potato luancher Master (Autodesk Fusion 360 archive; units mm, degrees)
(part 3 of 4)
sketch "Sketch5" plane through (-5, 0, 0) normal (-1, 0, 0) x axis (0, -1, 0)
  line L1 (-319.7775, 137.65) -> (-315.5775, 141.85)
  line L2 (-319.7775, 135.65) -> (-319.7775, 137.65)
  line L3 (-313.4688, 135.65) -> (-319.7775, 135.65)
  line L4 (-313.4688, 131.35) -> (-313.4688, 135.65)
  line L5 (-278.9967, 136.85) -> (-278.9967, 123.4258)
  line L6 (-272.0357, 136.85) -> (-278.9967, 136.85)
  line L7 (-263.8509, 141.85) -> (-260.0435, 127.6406)
  line L8 (-296.5763, 141.85) -> (-279.0207, 162.9256)
  line L9 (-315.5775, 141.85) -> (-296.5763, 141.85)
  line L10 (-268.93, 125.2594) -> (-272.0357, 136.85)
  line L11 (-270.1342, 165.3063) -> (-263.8509, 141.85)
  arc A1 centre (-229.7424, 131.35) radius 83.7264 clockwise from (-311.5111, 113.35) to (-313.4688, 131.35)
  arc A2 centre (-274.4187, 51.1532) radius 72.4175 clockwise from (-311.5111, 113.35) to (-278.9967, 123.4258)
  arc A3 centre (-264.4867, 126.45) radius 4.6 clockwise from (-260.0435, 127.6406) to (-268.93, 125.2594)
  circle C1 centre (-264.4867, 126.45) radius 4.6
  arc A4 centre (-264.4867, 126.45) radius 39.2645 clockwise from (-279.0207, 162.9256) to (-270.1342, 165.3063)
  concentric A3 C1
extrude "Extrude3" add sketch "Sketch5" profile of A3 C1 blind 8 from offset 0.5
mirror "Mirror1" mirrorStitchTolerance 0.1
sketch "trigger pivot cleanup" plane through (0, 250.2367, 0) normal (0, -1, 0) x axis (1, 0, 0)
  line L1 (0, 173.45) -> (0, 116.35)
  line L2 (0, 116.35) -> (0, 173.45)
  line L3 (7.8919, 122.4898) -> (12.2469, 130.6973)
  line L4 (17.2316, 117.5341) -> (7.8919, 122.4898)
  line L5 (21.5865, 125.7415) -> (17.2316, 117.5341)
  line L6 (12.2469, 130.6973) -> (21.5865, 125.7415)
  line L7 (-9.193, 120.0119) -> (-12.5429, 130.6973)
  line L8 (-22.3256, 115.8947) -> (-9.193, 120.0119)
  line L9 (-25.6756, 126.58) -> (-22.3256, 115.8947)
  line L10 (-12.5429, 130.6973) -> (-25.6756, 126.58)
  arc A1 centre (0, 108.45) radius 65 clockwise from (-16, 171.45) to (0, 173.45)
  arc A2 centre (73.7256, 152.4) radius 91.7256 clockwise from (-11.4459, 118.35) to (-16, 171.45)
  arc A3 centre (0, 150.1021) radius 33.7521 clockwise from (0, 116.35) to (-11.4459, 118.35)
  arc A4 centre (0, 150.1021) radius 33.7521 clockwise from (11.4459, 118.35) to (0, 116.35)
  arc A5 centre (-73.7256, 152.4) radius 91.7256 clockwise from (16, 171.45) to (11.4459, 118.35)
  arc A6 centre (0, 108.45) radius 65 clockwise from (0, 173.45) to (16, 171.45)
  perpendicular L3 L4
  parallel L3 L5
  parallel L4 L6
  perpendicular L7 L8
  parallel L7 L9
  parallel L8 L10
extrude "Extrude8" cut sketch "trigger pivot cleanup" profile of A2 A5 L4 L5 L6 L8 L9 L10 against normal blind 20.32
combine "Combine1"
sketch "Sketch4" plane through (0, 0, 0) normal (1, 0, 0) x axis (0, 1, 0)
  line L1 (315.4811, 135.35) -> (315.4811, 131.35)
  line L2 (321.7775, 135.35) -> (315.4811, 135.35)
  line L3 (415.956, 135.35) -> (321.7775, 135.35)
  line L4 (415.956, 131.35) -> (415.956, 135.35)
  line L5 (315.4811, 131.35) -> (415.956, 131.35)
  line L6 (276.256, 131.35) -> (277.081, 131.35)
  line L7 (276.256, 131.35) -> (272.2367, 116.35)
  line L8 (250.2367, 116.35) -> (272.2367, 116.35)
  line L9 (250.2367, 173.45) -> (250.2367, 116.35)
  line L10 (415.956, 173.45) -> (250.2367, 173.45)
  line L11 (415.956, 169.45) -> (415.956, 173.45)
  line L12 (322.8085, 169.45) -> (415.956, 169.45)
  line L13 (254.2367, 169.45) -> (322.8085, 169.45)
  line L14 (254.2367, 120.35) -> (254.2367, 169.45)
  line L15 (269.1674, 120.35) -> (254.2367, 120.35)
  line L16 (269.1674, 120.35) -> (273.1866, 135.35)
  line L17 (275.635, 135.35) -> (273.1866, 135.35)
  line L18 (476.756, 88.9) -> (476.756, -88.9)
  line L19 (44.956, 88.9) -> (44.956, -88.9)
  line L20 (282.1228, 88.9) -> (476.756, 88.9)
  line L21 (466.756, 88.9) -> (415.956, 88.9)
  line L22 (415.956, 173.45) -> (456.3745, 173.45)
  line L23 (415.956, 88.9) -> (415.956, 173.45)
  line L24 (466.756, 88.9) -> (456.3745, 173.45)
  line L25 (322.7775, 173.45) -> (415.956, 173.45)
  line L26 (322.7775, 131.35) -> (322.7775, 173.45)
  line L27 (415.956, 131.35) -> (322.7775, 131.35)
  line L28 (415.956, 173.45) -> (415.956, 131.35)
  line L29 (410.7438, 131.35) -> (415.956, 88.9)
  line L30 (277.081, 131.35) -> (275.635, 135.35)
  point P21 (476.756, 88.9)
  point P24 (476.756, 88.9)
  point P26 (415.956, 88.9)
  point P6 (415.956, 131.35)
  point P32 (322.7775, 131.35)
  point P13 (415.956, 173.45)
  point P30 (415.956, 173.45)
  point P34 (410.7438, 131.35)
  point P27 (466.756, 88.9)
  point P4 (321.7775, 135.35)
  coincident P21 P24
  perpendicular L18 L20
  horizontal L21
  horizontal L22
  vertical L23
  coincident L20 P26
  coincident P6 L23
  horizontal L25
  vertical L26
  horizontal L27
  vertical L28
  coincident L5 P32
  coincident P13 P30
  coincident L22 P30
  coincident L27 P34
  parallel L24 L29
  dimension "d439" distance P26 P27 = 50.8
  dimension "d440" angle L22 L24 = 97 (= "90 deg + 7 deg")
  dimension "d441" distance P4 L26 = 1
work_plane "WorkPlane1" RotateAngle 90
split "Split2" bodies "left (1)", "right (1)"
remove_body "RemoveBody1"
remove_body "RemoveBody2"
sketch "Sketch5" plane through (0, 420.5316, 51.6348) normal (0, 0.9925, 0.1219) x axis (0, -0.1219, 0.9925)
  line L1 (-15.8537, 0) -> (0, 0)
  line L2 (26.4239, -25.4) -> (110.1588, -17.5985)
  line L3 (26.4239, 0) -> (26.4239, -25.4)
  line L4 (31.3541, 0) -> (116.5391, 0)
  line L5 (26.4239, 25.4) -> (110.1588, 17.5985)
  line L6 (26.4239, 0) -> (26.4239, 25.4)
  closed curve K1 centre (57.2419, 0)
  closed curve K2 centre (57.2419, 0)
  closed curve K3 centre (101.5219, -73.7256)
  closed curve K4 centre (101.5219, 73.7256)
  point P1 (0, 0)
  point P13 (0, 0)
  point P12 (31.2476, 0)
  point P15 (110.1588, -17.5985)
  point P17 (26.4239, 0)
  point P21 (110.1588, 17.5985)
  point P16 (26.4239, -25.4)
  point P20 (26.4239, 25.4)
  point P22 (26.4239, 0)
  point P3 (122.73, 0)
  coincident P1 P13
  horizontal L1
  coincident P12 L1
  coincident K4 P15
  vertical L3
  coincident L1 P17
  tangent K4 L2
  symmetric P15 L4 P21
  symmetric P16 L4 P20
  symmetric P17 L4 P22
  dimension "d447" distance P16 P17 = 25.4
  dimension "d451" distance P3 L6 = 96.3061
work_plane "WorkPlane19" AlongDistance -228.6
sketch "Sketch33" plane through (0, 478.8367, 0) normal (0, -1, 0) x axis (-1, 0, 0)
  line L1 (0, -77.8617) -> (25.4, -77.8617)
  line L2 (25.4, -77.8617) -> (17.5985, -160.9724)
  line L3 (-25.4, -77.8617) -> (-17.5985, -160.9724)
  line L4 (0, -77.8617) -> (-25.4, -77.8617)
  arc A1 centre (-73.7256, -152.4) radius 91.7256 clockwise from (16, -133.35) to (16, -171.45)
  arc A2 centre (0, -108.45) radius 65 clockwise from (16, -171.45) to (0, -173.45)
  arc A3 centre (0, -108.45) radius 65 clockwise from (0, -173.45) to (-16, -171.45)
  arc A4 centre (73.7256, -152.4) radius 91.7256 clockwise from (-16, -171.45) to (-16, -133.35)
loft "Loft4" sketch "Sketch5" + "Sketch33"
sketch "Sketch6" plane through (0, 0, 0) normal (1, 0, 0) x axis (0, 1, 0)
  line L1 (476.756, 88.9) -> (476.756, -88.9)
  line L2 (44.956, 88.9) -> (44.956, -88.9)
  line L3 (364.3526, 88.9) -> (476.756, 88.9)
  line L4 (405.8201, 171.45) -> (417.3113, 77.8617)
  line L5 (478.8367, 171.45) -> (405.8201, 171.45)
  line L6 (478.8367, 171.45) -> (478.8367, 77.8617)
  line L7 (417.3113, 77.8617) -> (478.8367, 77.8617)
  line L8 (405.5745, 173.45) -> (405.8201, 171.45)
  line L9
  line L10 (478.8367, 173.45) -> (478.8367, 171.45)
  line L11 (405.8201, 171.45) -> (478.8367, 171.45)
  line L12 (405.5745, 173.45) -> (478.8367, 173.45)
  line L13 (466.756, 88.9) -> (415.956, 88.9)
  line L14 (472.7065, 40.4371) -> (454.8153, 186.1492)
  line L15 (487.1508, 88.9) -> (407.438, 88.9)
  line L16 (487.1508, 75.9737) -> (487.1508, 88.9)
  line L17 (407.438, 75.9737) -> (487.1508, 75.9737)
  line L18 (407.438, 88.9) -> (407.438, 75.9737)
  point P3 (476.756, 88.9)
  point P6 (476.756, 88.9)
  point P15 (478.8367, 173.45)
  point P16 (478.8367, 173.45)
  point P13 (405.5745, 173.45)
  point P17 (405.5745, 173.45)
  point P21 (415.956, 88.9)
  point P22 (415.956, 88.9)
  point P23 (466.756, 88.9)
  point P26 (407.438, 88.9)
  coincident P3 P6
  perpendicular L1 L3
  coincident P15 P16
  coincident P13 P17
  coincident L4 P21
  coincident L3 P21
  coincident P21 P22
  parallel L3 L13
  coincident P23 L14
  parallel L4 L14
  horizontal L15
  vertical L16
  horizontal L17
  vertical L18
  coincident L3 P26
  dimension "d452" distance P22 P23 = 50.8
extrude "Extrude5" cut sketch "Sketch6" profile of L1 L3 L5 L6 L7 L9 L10 L11 L12 L14 L15 distance 88.9
revolve "Revolve1" sketch "Sketch6" AlongAngle 360
shell "Shell2" innerThickness 4
split "Split3"
work_plane "WorkPlane2" AlongDistance -101.6
sketch "Sketch7" plane through (0, 351.8367, 0) normal (0, -1, 0) x axis (-1, 0, 0)
  arc A1 centre (0, -196.35) radius 61 clockwise from (-12.5765, -136.6605) to (0, -135.35)
  arc A2 centre (73.7256, -152.4) radius 87.7256 clockwise from (-12.5765, -168.1395) to (-12.5765, -136.6605)
  arc A3 centre (0, -108.45) radius 61 clockwise from (0, -169.45) to (-12.5765, -168.1395)
  arc A4 centre (0, -108.45) radius 61 clockwise from (12.5765, -168.1395) to (0, -169.45)
  arc A5 centre (-73.7256, -152.4) radius 87.7256 clockwise from (12.5765, -136.6605) to (12.5765, -168.1395)
  arc A6 centre (0, -196.35) radius 61 clockwise from (0, -135.35) to (12.5765, -136.6605)
  arc A7 centre (0, -196.35) radius 65 clockwise from (-6, -131.6275) to (0, -131.35)
  arc A8 centre (0, -196.35) radius 65 clockwise from (0, -131.35) to (6, -131.6275)
extrude "Extrude6" cut sketch "Sketch7" profile of A1 A2 A3 A4 A5 A6 against normal blind 76.2
combine "Combine2"
combine "Combine3"
face "Face1" sketch "Sketch4"
sketch "Sketch6" plane through (0, 0, 0) normal (1, 0, 0) x axis (0, 1, 0)
  line L1 (322.7775, 131.35) -> (410.7438, 131.35)
  line L2 (322.7775, 173.45) -> (322.7775, 131.35)
  line L3 (456.3745, 173.45) -> (322.7775, 173.45)
  line L4 (466.756, 88.9) -> (456.3745, 173.45)
  line L5 (415.956, 88.9) -> (466.756, 88.9)
  line L6 (410.7438, 131.35) -> (415.956, 88.9)
  line L7 (322.4775, 173.45) -> (322.7775, 173.45)
  line L8 (322.4775, 131.35) -> (322.4775, 173.45)
  line L9 (322.7775, 131.35) -> (322.4775, 131.35)
  line L10 (322.7775, 173.45) -> (322.7775, 131.35)
  point P4 (322.7775, 173.45)
  point P8 (322.7775, 173.45)
  point P3 (322.7775, 131.35)
  point P11 (322.7775, 131.35)
  point P10 (322.4775, 131.35)
  horizontal L7
  vertical L8
  horizontal L9
  vertical L10
  coincident P4 P8
  coincident P3 P11
  dimension "d442" distance P10 P11 = 0.3
extrude "Extrude4" cut sketch "Sketch6" distance 3.175
work_plane "WorkPlane21" AlongDistance 130.592 (= "120.592 mm + 10 mm")
sketch "Sketch1" plane through (0, 130.592, 0) normal (0, 1, 0) x axis (1, 0, 0)
  line L1 (-66.675, -62.217) -> (-63.5, -62.217)
  line L2 (-114.8533, -109.7881) -> (0, 0)
  line L3 (-71.5066, -77.9814) -> (-79.2206, -75.7268)
  line L4 (-65.6971, -72.4281) -> (-71.5066, -77.9814)
  line L5 (-67.6016, -64.6203) -> (-65.6971, -72.4281)
  line L6 (-75.3157, -62.3658) -> (-67.6016, -64.6203)
  line L7 (-81.1251, -67.9191) -> (-75.3157, -62.3658)
  line L8 (-79.2206, -75.7268) -> (-81.1251, -67.9191)
  line L9 (-64.2629, -61.4288) -> (-61.2638, -73.7238)
  line L10 (-76.4102, -57.8786) -> (-64.2629, -61.4288)
  line L11 (-85.5585, -66.6234) -> (-76.4102, -57.8786)
  line L12 (-82.5594, -78.9184) -> (-85.5585, -66.6234)
  line L13 (-70.412, -82.4686) -> (-82.5594, -78.9184)
  line L14 (-61.2638, -73.7238) -> (-70.412, -82.4686)
  circle C1 centre (0, 0) radius 88.9
  point P1 (0, 0)
  point P4 (0, 0)
  point P6 (-65.0875, -62.217)
  point P14 (-73.4111, -70.1736)
  point P8 (-79.2206, -75.7268)
  point P16 (-64.2629, -61.4288)
  coincident P1 P4
  midpoint L1 P6
  coincident L2 P6
  coincident L2 P14
  coincident L2 P8
  coincident C1 P16
  dimension "d486" distance P14 L8 = 6.96 (= "13.92 mm / 2")
  dimension "d487" = 4
work_plane "WorkPlane1" RotateAngle 90
sketch "Sketch2" plane through (-7.5732, 0, -7.9226) normal (-0.691, 0, -0.7229) x axis (-0.7229, 0, 0.691)
  line L1 (-88.9, 476.756) -> (88.9, 476.756)
  line L2 (-88.9, 44.956) -> (88.9, 44.956)
  line L3 (88.9, 476.756) -> (88.9, 44.956)
  line L4 (107.8833, 130.592) -> (95.2278, 130.592)
  line L5 (114.211, 130.592) -> (107.8833, 130.592)
  line L6 (95.2278, 130.592) -> (88.9, 130.592)
  line L7 (122.0173, 164.7525) -> (102.9, 130.592)
  line L8 (88.9, 170.592) -> (122.0173, 164.7525)
  line L9 (102.4196, 168.2081) -> (118.078, 165.4471)
  line L10 (111.2166, 218.0985) -> (102.4196, 168.2081)
  line L11 (126.875, 215.3375) -> (111.2166, 218.0985)
  line L12 (118.078, 165.4471) -> (126.875, 215.3375)
  line L13 (107.1949, 195.2903) -> (108.0631, 200.2144)
  line L14 (93.9, 197.6346) -> (107.1949, 195.2903)
  line L15 (94.7682, 202.5586) -> (93.9, 197.6346)
  line L16 (108.0631, 200.2144) -> (94.7682, 202.5586)
  line L17 (88.9, 130.592) -> (102.9, 130.592)
  line L18 (124.4623, 215.7629) -> (113.6294, 217.6731)
  line L19 (133.1447, 265.0033) -> (124.4623, 215.7629)
  line L20 (122.3118, 266.9134) -> (133.1447, 265.0033)
  line L21 (113.6294, 217.6731) -> (122.3118, 266.9134)
  line L22 (103.4044, 168.0345) -> (117.0932, 165.6208)
  line L23 (88.9, 130.592) -> (88.9, 170.592)
  line L24 (86.9, 130.592) -> (88.9, 130.592)
  line L25 (86.9, 170.592) -> (86.9, 130.592)
  line L26 (88.9, 170.592) -> (86.9, 170.592)
  point P4 (88.9, 44.956)
  point P6 (88.9, 44.956)
  point P2 (88.9, 476.756)
  point P7 (88.9, 476.756)
  point P14 (88.9, 170.592)
  point P20 (107.1949, 195.2903)
  point P23 (94.3341, 200.0966)
  point P24 (88.9, 130.592)
  point P8 (95.2278, 130.592)
  point P29 (119.0458, 216.718)
  point P30 (119.0458, 216.718)
  point P31 (117.0932, 165.6208)
  point P32 (103.4044, 168.0345)
  point P13 (122.0173, 164.7525)
  point P11 (88.9, 130.592)
  point P33 (88.9, 130.592)
  point P15 (118.078, 165.4471)
  point P18 (126.875, 215.3375)
  point P16 (102.4196, 168.2081)
  point P21 (93.9, 197.6346)
  point P22 (94.7682, 202.5586)
  point P10 (114.211, 130.592)
  point P27 (133.1447, 265.0033)
  point P28 (122.3118, 266.9134)
  point P26 (124.4623, 215.7629)
  point P12 (102.9, 130.592)
  point P35 (86.9, 170.592)
  coincident P4 P6
  coincident P2 P7
  coincident L3 P14
  perpendicular L9 L10
  parallel L9 L11
  parallel L10 L12
  perpendicular L13 L14
  parallel L13 L15
  parallel L14 L16
  coincident L10 P20
  parallel L10 L13
  midpoint L15 P23
  parallel L8 L9
  coincident L3 P24
  perpendicular L3 L17
  coincident P8 L17
  perpendicular L18 L19
  parallel L18 L20
  parallel L19 L21
  parallel L12 L19
  midpoint L18 P29
  midpoint L11 P30
  coincident P29 P30
  coincident L9 P31
  coincident L9 P32
  midpoint L9 L22
  coincident P13 L9
  perpendicular L23 L24
  parallel L23 L25
  parallel L24 L26
  coincident P11 P33
  dimension "d490" distance P15 P18 = 50.66
  dimension "d491" distance P15 P16 = 15.9
  dimension "d492" distance L10 L15 = 13.5
  dimension "d493" distance L9 P23 = 30
  dimension "d495" distance P21 P22 = 5
  dimension "d497" angle L3 L10 = 10
  dimension "d498" distance P10 P11 = 25.311
  dimension "d500" distance L3 P21 = 5
  dimension "d501" distance P14 L17 = 40
  dimension "d502" distance P27 P28 = 11
  dimension "d504" distance P26 P27 = 50
  dimension "d505" distance P31 P32 = 13.9
  dimension "d506" distance P13 P31 = 5
  dimension "d507" distance L3 P12 = 14
  dimension "d511" distance P14 P35 = 2
face "Face1" sketch "Sketch2" bodies "right"
work_plane "WorkPlane1" RotateAngle 90
mirror "Mirror1" mirrorStitchTolerance 0.1 bodies "left"
sketch "Sketch1" plane through (-16.4132, -12.7068, 15.6894) normal (-0.6308, -0.4884, 0.603) x axis (0.6122, -0.7907, 0)
  line L1 (-144.1616, 79.3929) -> (-179.6329, 95.9517)
  line L2 (-142.8185, 82.2699) -> (-144.1616, 79.3929)
  line L3 (-178.2899, 98.8286) -> (-142.8185, 82.2699)
  line L4 (-179.6329, 95.9517) -> (-178.2899, 98.8286)
  line L5 (-188.9051, 76.0893) -> (-153.4337, 59.5305)
  line L6 (-190.2481, 73.2123) -> (-188.9051, 76.0893)
  line L7 (-154.7767, 56.6536) -> (-190.2481, 73.2123)
  line L8 (-153.4337, 59.5305) -> (-154.7767, 56.6536)
  line L9 (-190.2481, 73.2123) -> (-178.2899, 98.8286)
  line L10 (-154.7767, 56.6536) -> (-190.2481, 73.2123)
  line L11 (-142.8185, 82.2699) -> (-154.7767, 56.6536)
  line L12 (-178.2899, 98.8286) -> (-142.8185, 82.2699)
  point P8 (-190.2481, 73.2123)
  point P11 (-190.2481, 73.2123)
  point P5 (-178.2899, 98.8286)
  point P10 (-178.2899, 98.8286)
  perpendicular L9 L10
  parallel L9 L11
  parallel L10 L12
  coincident P8 P11
  perpendicular L7 L9
  coincident P5 P10
face "Face2" sketch "Sketch1" bodies "top"
sketch "Sketch2" plane through (0, 130.592, 0) normal (0, -1, 0) x axis (1, 0, 0)
  line L1 (-55.2439, 67.9694) -> (-66.8098, 79.0252)
  line L2 (-64.6159, 81.3203) -> (-53.05, 70.2645)
  line L3 (-66.8098, 79.0252) -> (-64.6159, 81.3203)
  line L4 (-81.9562, 63.18) -> (-70.3904, 52.1242)
  line L5 (-84.1501, 60.8849) -> (-81.9562, 63.18)
  line L6 (-72.5842, 49.8291) -> (-84.1501, 60.8849)
  line L7 (-84.1501, 60.8849) -> (-64.6159, 81.3203)
  line L8 (-72.5842, 49.8291) -> (-84.1501, 60.8849)
  line L9 (-53.05, 70.2645) -> (-72.5842, 49.8291)
  line L10 (-64.6159, 81.3203) -> (-53.05, 70.2645)
  line L11 (-53.05, 70.2645) -> (-55.2439, 67.9694)
  line L12 (-70.3904, 52.1242) -> (-72.5842, 49.8291)
  point P8 (-84.1501, 60.8849)
  point P11 (-84.1501, 60.8849)
  point P5 (-64.6159, 81.3203)
  point P10 (-64.6159, 81.3203)
  point P9 (-72.5842, 49.8291)
  perpendicular L7 L8
  parallel L7 L9
  parallel L8 L10
  coincident P8 P11
  perpendicular L6 L7
  coincident P5 P10
  coincident P9 L9
face "Face3" sketch "Sketch2" bodies "back"
sketch "Sketch3" plane through (-23.0259, 180.6508, 22.0104) normal (-0.1255, 0.9848, 0.12) x axis (-0.992, -0.1264, 0)
  line L1 (59.1509, 70.7356) -> (34.6654, 47.6855)
  line L2 (56.9747, 73.0474) -> (59.1509, 70.7356)
  line L3 (32.4891, 49.9973) -> (56.9747, 73.0474)
  line L4 (76.3521, 52.4632) -> (56.9747, 73.0474)
  line L5 (78.5349, 54.5181) -> (76.3521, 52.4632)
  line L6 (59.1574, 75.1022) -> (78.5349, 54.5181)
  line L7 (56.9747, 73.0474) -> (59.1574, 75.1022)
  line L8 (49.6903, 31.7249) -> (74.1758, 54.775)
  line L9 (76.3521, 52.4632) -> (51.8665, 29.4131)
  line L10 (74.1758, 54.775) -> (76.3521, 52.4632)
  line L11 (78.5349, 54.5181) -> (51.8665, 29.4131)
  line L12 (59.1574, 75.1022) -> (78.5349, 54.5181)
  line L13 (32.4891, 49.9973) -> (59.1574, 75.1022)
  line L14 (51.8665, 29.4131) -> (32.4891, 49.9973)
  line L15 (34.6654, 47.6855) -> (32.4891, 49.9973)
  line L16 (51.8665, 29.4131) -> (49.6903, 31.7249)
  line L17 (48.2561, 30.3749) -> (49.6903, 31.7249)
  line L18 (50.4324, 28.0631) -> (48.2561, 30.3749)
  line L19 (51.8665, 29.4131) -> (50.4324, 28.0631)
  line L20 (49.6903, 31.7249) -> (51.8665, 29.4131)
  line L21 (34.6654, 47.6855) -> (33.2312, 46.3354)
  line L22 (32.4891, 49.9973) -> (34.6654, 47.6855)
  line L23 (31.055, 48.6472) -> (32.4891, 49.9973)
  line L24 (33.2312, 46.3354) -> (31.055, 48.6472)
  line L25 (48.2561, 30.3749) -> (33.2312, 46.3354)
  point P8 (78.5349, 54.5181)
  point P15 (78.5349, 54.5181)
  point P12 (51.8665, 29.4131)
  point P14 (51.8665, 29.4131)
  point P22 (33.2312, 46.3354)
  point P26 (33.2312, 46.3354)
  point P19 (48.2561, 30.3749)
  point P27 (48.2561, 30.3749)
  perpendicular L11 L12
  parallel L11 L13
  parallel L12 L14
  coincident P8 P15
  perpendicular L6 L11
  coincident P12 P14
  coincident P22 P26
  coincident P19 P27
face "Face4" sketch "Sketch3" bodies "face"
sketch "Sketch4" plane through (-23.4245, 183.7776, 22.3914) normal (-0.1255, 0.9848, 0.12) x axis (-0.992, -0.1264, 0)
  line L1 (78.5349, 54.5181) -> (50.4324, 28.0631)
  line L2 (59.1574, 75.1022) -> (78.5349, 54.5181)
  line L3 (31.055, 48.6472) -> (59.1574, 75.1022)
  line L4 (50.4324, 28.0631) -> (31.055, 48.6472)
  line L5 (40.7437, 38.3551) -> (68.8462, 64.8101)
  line L6 (51.8665, 29.4131) -> (76.3521, 52.4632)
  line L7 (56.9747, 73.0474) -> (76.3521, 52.4632)
  circle C1 centre (58.7013, 55.26) radius 6.935
  circle C2 centre (58.7013, 55.26) radius 4.15
  point P7 (68.8462, 64.8101)
  point P8 (40.7437, 38.3551)
  point P6 (58.7013, 55.26)
  point P9 (63.7509, 60.0136)
  point P11 (76.3521, 52.4632)
  point P13 (76.3521, 52.4632)
  point P14 (56.9747, 73.0474)
  midpoint L2 P7
  midpoint L4 P8
  coincident P6 L5
  coincident L5 P9
  coincident C1 P9
  concentric C1 C2
  coincident P11 P13
  coincident L3 P14
  perpendicular L3 L7
  dimension "d513" diameter C1 = 13.87
  dimension "d514" diameter C2 = 8.3
  dimension "d515" distance P9 L7 = 4
extrude "Extrude1" cut sketch "Sketch4" profile of C2 against normal blind 3.175
offset_faces "OffsetFaces1" distance -1
loft "Loft1"
sketch "Sketch46" plane through (-23.4245, 183.7776, 22.3914) normal (-0.1255, 0.9848, 0.12) x axis (-0.992, -0.1264, 0)
  line L1 (77.8068, 53.8326) -> (50.4324, 28.0631)
  line L2 (58.4293, 74.4168) -> (77.8068, 53.8326)
  line L3 (31.055, 48.6472) -> (58.4293, 74.4168)
  line L4 (50.4324, 28.0631) -> (31.055, 48.6472)
  circle C1 centre (58.7013, 55.26) radius 4.15
extrude "Extrude2" cut sketch "Sketch46" profile of C1 against normal blind 5.175 (magnitude of "-0.125 in - 2 mm")
sketch "inlet body jig base" plane through (-62.8171, 0, 60.0468) normal (0.7229, 0, -0.691) x axis (0, 1, 0)
  line L1 (130.592, 10.96) -> (170.592, 10.96)
  line L2 (130.592, -10.96) -> (130.592, 10.96)
  line L3 (170.592, -10.96) -> (130.592, -10.96)
  line L4 (170.592, 10.96) -> (170.592, -10.96)
  line L5 (170.36, -10.96) -> (130.592, 10.96)
  line L6 (144.3456, 4.7162) -> (145.7598, 6.1304)
  line L7 (155.1922, -6.1304) -> (144.3456, 4.7162)
  line L8 (156.6064, -4.7162) -> (155.1922, -6.1304)
  line L9 (145.7598, 6.1304) -> (156.6064, -4.7162)
  line L10 (155.1922, -6.1304) -> (145.7598, 6.1304)
  line L11 (150.476, 13.5357) -> (150.476, 0)
  line L12 (155.1922, 6.1304) -> (144.3456, -4.7162)
  line L13 (145.7598, -6.1304) -> (156.6064, 4.7162)
  line L14 (156.6064, 4.7162) -> (155.1922, 6.1304)
  line L15 (144.3456, -4.7162) -> (145.7598, -6.1304)
  point P3 (130.592, 10.96)
  point P6 (130.592, 10.96)
  point P7 (170.36, -10.96)
  point P8 (150.476, 0)
  point P13 (150.476, 0)
  point P14 (150.476, 0)
  point P9 (145.7598, 6.1304)
  point P17 (155.1922, 6.1304)
  point P10 (144.3456, 4.7162)
  point P18 (156.6064, 4.7162)
  point P11 (155.1922, -6.1304)
  point P19 (145.7598, -6.1304)
  point P12 (156.6064, -4.7162)
  point P16 (144.3456, -4.7162)
  coincident P3 P6
  coincident L3 P7
  midpoint L5 P8
  perpendicular L6 L7
  parallel L6 L8
  parallel L7 L9
  midpoint L10 P13
  coincident P8 P13
  coincident P13 P14
  vertical L11
  symmetric P9 L11 P17
  symmetric P10 L11 P18
  symmetric P11 L11 P19
  symmetric P12 L11 P16
  dimension "d572" distance P11 P12 = 2
  dimension "d573" distance P9 P12 = 15.3394
  dimension "d574" angle L1 L9 = 45
extrude "Extrude2" cut sketch "inlet body jig base" profile of L6 L7 L8 L9 L12 L13 L14 L15 against normal blind 1
hole "Hole1" HoleDepth 17.78 HoleDiameter 10.8204 TipAngle 180
remove_instance "RemoveInstance1"
sketch "Sketch3" plane through (0, 0, 0) normal (0, 0, 1) x axis (1, 0, 0)
  circle C1 centre (13.7901, 221.4962) radius 17.4625
  circle C2 centre (13.7901, 221.4962) radius 3.325
  concentric C1 C2
  dimension "d586" diameter C1 = 34.925
  dimension "d587" diameter C2 = 6.65 (= "0.25 in + 0.3 mm")
face "Face1" sketch "Sketch3"
joint "Assemble1" alignAngle 0 alignOffsetX 0 alignOffsetY 0 alignOffsetZ 0
sketch "claw init" plane through (-22.4118, 0, 40.4319) normal (0.4848, 0, -0.8746) x axis (0.8746, 0, 0.4848)
  line L1 (24.13, 0) -> (-24.13, 0)
  line L2 (88.9, -44.956) -> (-88.9, -44.956)
  line L3 (-40.4813, 68.326) -> (-34.4813, 68.326)
  line L4 (-32.0572, 81.026) -> (-24.246, 100.743)
  line L5 (-70.2879, 68.326) -> (-34.4813, 68.326)
  line L6 (-47.2124, 70.5709) -> (-34.4813, 68.326)
  line L7 (-42.4813, 47.6884) -> (-42.4813, 82.326)
  line L8 (0, -22.5) -> (0, -1.75)
  line L9 (88.9, 177.8645) -> (-88.9, 177.8645)
  line L10 (88.9, -41.2125) -> (88.9, 177.8645)
  line L11 (-88.9, -41.2125) -> (88.9, -41.2125)
  line L12 (-88.9, 177.8645) -> (-88.9, -41.2125)
  line L13 (-55.1813, 69.626) -> (-42.4813, 69.626)
  line L14 (-55.1813, 13.4637) -> (-55.1813, 69.626)
  line L15 (-42.4813, 13.4637) -> (-55.1813, 13.4637)
  line L16 (-42.4813, 69.626) -> (-42.4813, 13.4637)
  line L17 (-42.4813, 47.6884) -> (-30.4657, 23.9497)
  line L18 (-55.1813, 44.6574) -> (-41.7968, 18.2143)
  line L19 (-40.4813, 68.326) -> (-34.4813, 68.326)
  line L20 (-55.1813, 44.6574) -> (-42.4813, 47.6884)
  line L21 (-48.8313, 46.1729) -> (-34.4813, 68.326)
  line L22 (-36.1313, 21.082) -> (-48.8313, 46.1729)
  line L23 (-46.0984, 26.7127) -> (-34.7672, 32.4481)
  circle C1 centre (29.561, 75.0731) radius 1.61
  circle C2 centre (13.1559, 95.6445) radius 1.61
  circle C3 centre (23.7061, 49.421) radius 1.61
  circle C4 centre (-13.1559, 95.6445) radius 1.61
  circle C5 centre (-29.561, 75.0731) radius 1.61
  circle C6 centre (0, 38.0048) radius 1.61
  circle C7 centre (-23.7061, 49.421) radius 1.61
  arc A1 centre (0, 68.326) radius 34.4813 clockwise from (-34.4813, 68.326) to (-32.0572, 81.026)
  arc A2 centre (0, 68.326) radius 40.4813 clockwise from (-24.246, 100.743) to (-40.4813, 68.326)
  arc A3 centre (-50.7312, 68.326) radius 16.25 clockwise from (-42.4813, 82.326) to (-34.4813, 68.326)
  arc A4 centre (-42.4813, 69.626) radius 12.7 clockwise from (-55.1813, 69.626) to (-42.4813, 82.326)
  arc A5 centre (-24.13, -69.1365) radius 69.1365 clockwise from (-88.9, -44.956) to (-24.13, 0)
  circle C8 centre (-36.1313, 21.082) radius 3.175
  circle C9 centre (-36.1313, 21.082) radius 6.35
  circle C10 centre (-48.8313, 46.1729) radius 3.175
  arc A6 centre (29.561, 75.0731) radius 3 clockwise from (28.0113, 72.5044) to (27.0503, 76.7151)
  arc A7 centre (0, 68.326) radius 28.3213 clockwise from (28.0113, 72.5044) to (23.4244, 52.4078)
  arc A8 centre (23.7061, 49.421) radius 3 clockwise from (20.7316, 49.031) to (23.4244, 52.4078)
  arc A9 centre (0, 68.326) radius 28.3213 clockwise from (20.7316, 49.031) to (2.1595, 40.0872)
  arc A10 centre (0, 38.0048) radius 3 clockwise from (-2.1595, 40.0872) to (2.1595, 40.0872)
  arc A11 centre (0, 68.326) radius 28.3213 clockwise from (-2.1595, 40.0872) to (-20.7316, 49.031)
  arc A12 centre (-23.7061, 49.421) radius 3 clockwise from (-23.4244, 52.4078) to (-20.7316, 49.031)
  arc A13 centre (0, 68.326) radius 28.3213 clockwise from (-23.4244, 52.4078) to (-28.0113, 72.5044)
  arc A14 centre (-29.561, 75.0731) radius 3 clockwise from (-27.0503, 76.7151) to (-28.0113, 72.5044)
  arc A15 centre (0, 68.326) radius 28.3213 clockwise from (-27.0503, 76.7151) to (-14.198, 92.8313)
  arc A16 centre (-13.1559, 95.6445) radius 3 clockwise from (-10.3067, 94.7052) to (-14.198, 92.8313)
  arc A17 centre (0, 68.326) radius 28.3213 clockwise from (-10.3067, 94.7052) to (10.3067, 94.7052)
  arc A18 centre (13.1559, 95.6445) radius 3 clockwise from (14.198, 92.8313) to (10.3067, 94.7052)
  arc A19 centre (0, 68.326) radius 28.3213 clockwise from (14.198, 92.8313) to (27.0503, 76.7151)
  point P15 (-34.4813, 68.326)
  point P18 (-34.4813, 68.326)
  point P20 (-34.4813, 68.326)
  point P25 (0, 27.8447)
  point P10 (0, 68.326)
  point P32 (0, 68.326)
  point P33 (0, 177.8645)
  point P34 (-42.4813, 69.626)
  point P39 (-55.1813, 69.626)
  point P38 (-42.4813, 69.626)
  point P2 (-24.13, 0)
  point P41 (-24.13, 0)
  point P4 (-88.9, -44.956)
  point P40 (-88.9, -44.956)
  point P45 (-30.4657, 23.9497)
  point P46 (-41.7968, 18.2143)
  point P47 (-55.1813, 44.6574)
  point P50 (-48.8313, 46.1729)
  point P51 (-48.8313, 46.1729)
  point P48 (-34.4813, 68.326)
  point P52 (-34.4813, 68.326)
  point P53 (-48.8313, 46.1729)
  point P54 (-48.8313, 46.1729)
  point P43 (-36.1313, 21.082)
  point P55 (-36.1313, 21.082)
  point P56 (-34.7672, 32.4481)
  point P57 (-46.0984, 26.7127)
  point P58 (-33.2636, 15.4164)
  point P16 (-40.4813, 68.326)
  point P22 (-42.4813, 82.326)
  point P28 (-88.9, 177.8645)
  point P29 (88.9, 177.8645)
  point P35 (-55.1813, 69.626)
  point P49 (-40.4813, 68.326)
  coincident P15 P18
  parallel L3 L5
  coincident P15 P20
  vertical L7
  tangent A1 A3
  coincident A2 P25
  coincident P25 L8
  horizontal L9
  perpendicular L9 L10
  parallel L9 L11
  parallel L10 L12
  coincident P10 P32
  midpoint L9 P33
  coincident L8 P33
  horizontal L13
  vertical L14
  horizontal L15
  vertical L16
  coincident L7 P34
  coincident L13 P39
  coincident P34 P38
  coincident L14 P39
  coincident P2 P41
  coincident P4 P40
  coincident C9 P45
  tangent C9 L17
  coincident C9 P46
  tangent C9 L18
  coincident L14 P47
  parallel L17 L18
  tangent L16 C9
  midpoint L20 P50
  coincident P50 P51
  coincident P48 P52
  coincident P51 P53
  coincident P51 P54
  coincident P43 P55
  coincident L17 P56
  coincident L18 P57
  perpendicular L18 L23
  coincident C9 P58
  coincident L22 P58
  dimension "d475" angle L5 L6 = 10
  dimension "d476" distance P16 L7 = 2
  dimension "d477" distance L5 P22 = 14
  dimension "d478" distance P28 P29 = 177.8 (= "7")
  dimension "d519" distance P34 P35 = 12.7
  dimension "d520" diameter C8 = 6.35
  dimension "d521" distance C8 = 3.175
  dimension "d535" distance P48 P49 = 6
  dimension "d536" diameter C10 = 6.35
  dimension "d537" distance L23 P58 = 15.875
  dimension "d756" distance P54 P55 = 28.1219
  dimension "d757" distance L13 P51 = 23.4531 (= "1.0033510731 in - 0.08 in")
face "Face1" sketch "claw init"
sketch "claw bend" plane through (-23.1814, 0, 41.8204) normal (0.4848, 0, -0.8746) x axis (0.8746, 0, 0.4848)
  line L1 (-30.4657, 23.9497) -> (-42.4813, 47.6884)
  line L2 (-55.1813, 44.6574) -> (-41.7968, 18.2143)
  line L3 (-55.1813, 69.626) -> (-55.1813, 44.6574)
  line L4 (-42.4813, 69.7366) -> (-34.4813, 68.326)
  line L5 (-42.4813, 47.6884) -> (-42.4813, 69.7366)
  line L6 (-46.0984, 26.7127) -> (-34.7672, 32.4481)
  arc A1 centre (-36.1313, 21.082) radius 6.35 clockwise from (-30.4657, 23.9497) to (-41.7968, 18.2143)
  arc A2 centre (-42.4813, 69.626) radius 12.7 clockwise from (-55.1813, 69.626) to (-42.4813, 82.326)
  arc A3 centre (-50.7312, 68.326) radius 16.25 clockwise from (-42.4813, 82.326) to (-34.4813, 68.326)
  circle C1 centre (-36.1313, 21.082) radius 3.175
  circle C2 centre (-48.8313, 46.1729) radius 3.175
sketch "Sketch49" plane through (0, 476.756, 0) normal (0, 1, 0) x axis (-1, 0, 0)
  line L1 (-49.3991, 88.7823) -> (-43.2242, 77.6845)
  line L2 (-52.1735, 87.2385) -> (-49.3991, 88.7823)
  line L3 (-45.9987, 76.1408) -> (-52.1735, 87.2385)
  line L4 (-43.2242, 77.6845) -> (-45.9987, 76.1408)
  line L5 (0, 88.9) -> (1.5875, 88.9)
  curve K1 (24.6922, 85.402) -> (16, 171.45)
  curve K2 (16, 171.45) -> (1.5875, 173.4306)
  line L6 (1.5875, 88.9) -> (1.5875, 173.4306)
  line L7 (-1.5875, 173.4306) -> (-1.5875, 88.9)
  curve K3 (-1.5875, 173.4306) -> (-16, 171.45)
  curve K4 (-16, 171.45) -> (-24.6922, 85.402)
  line L8 (-1.5875, 88.9) -> (0, 88.9)
  line L9 (8.3285, 88.509) -> (1.5875, 95.25)
  line L10 (0, 22.5) -> (0, 1.75)
  line L11 (-8.3285, 88.509) -> (-1.5875, 95.25)
  arc A1 centre (0, 0) radius 88.9 clockwise from (0, 88.9) to (24.6922, 85.402)
  arc A2 centre (0, 0) radius 88.9 clockwise from (-24.6922, 85.402) to (0, 88.9)
  point P18 (1.5875, 95.25)
  point P19 (8.3285, 88.509)
  point P22 (-1.5875, 95.25)
  point P23 (-8.3285, 88.509)
  point P6 (1.5875, 88.9)
  coincident L6 P18
  coincident A1 P19
  symmetric P18 L10 P22
  symmetric P19 L10 P23
  dimension "d579" angle L6 L9 = 135
  dimension "d580" distance P6 P18 = 6.35
extrude "Extrude9" cut sketch "Sketch49" profile of L5 A1 L6 L7 A2 L8 L9 L11 against normal blind 81.28
fillet "Fillet1" radius 5.08 5.08
sketch "Sketch50" plane through (1.5875, 0, 0) normal (1, 0, 0) x axis (0, 1, 0)
  line L1 (415.956, 88.9) -> (410.7438, 131.35)
  line L2 (466.756, 88.9) -> (415.956, 88.9)
  line L3 (456.3745, 173.45) -> (466.756, 88.9)
  line L4 (322.7775, 173.45) -> (456.3745, 173.45)
  line L5 (322.7775, 131.35) -> (322.7775, 173.45)
  line L6 (410.7438, 131.35) -> (322.7775, 131.35)
  line L7 (277.468, 157.1295) -> (278.2443, 160.0273)
  line L8 (277.468, 157.1295) -> (269.3594, 162.4081)
  line L9 (335.2775, 162.4081) -> (269.3594, 162.4081)
  line L10 (347.7775, 159.7411) -> (322.7775, 159.7411)
  line L11 (347.7775, 165.0751) -> (347.7775, 159.7411)
  line L12 (322.7775, 165.0751) -> (347.7775, 165.0751)
  line L13 (322.7775, 159.7411) -> (322.7775, 165.0751)
  line L14 (347.7775, 165.0751) -> (322.7775, 159.7411)
  line L15 (322.7775, 165.0751) -> (347.7775, 159.7411)
  line L16 (269.358, 162.4084) -> (268.5817, 159.5106)
  point P9 (277.468, 157.1295)
  point P11 (277.468, 157.1295)
  point P12 (273.4137, 159.7688)
  point P18 (335.2775, 162.4081)
  point P14 (322.7775, 159.7411)
  point P13 (335.2775, 162.4081)
  point P15 (347.7775, 159.7411)
  point P16 (347.7775, 165.0751)
  point P17 (322.7775, 165.0751)
  coincident P9 P11
  midpoint L8 P12
  perpendicular L5 L9
  horizontal L10
  perpendicular L10 L11
  parallel L10 L12
  parallel L11 L13
  coincident L14 P18
  coincident L15 P18
  coincident L5 P14
  coincident P13 P18
  dimension "d597" distance P15 P16 = 5.334
  dimension "d598" distance P16 P17 = 25
extrude "Extrude1" cut sketch "Sketch50" profile of L5 L10 L11 L12 L13 against normal blind 3.175
sketch "aft reif jig" plane through (0, 476.756, 0) normal (0, -1, 0) x axis (1, 0, 0)
  line L1 (1.5875, 173.45) -> (-1.5875, 173.45)
  line L2 (1.5875, 88.9) -> (1.5875, 173.45)
  line L3 (-1.5875, 88.9) -> (1.5875, 88.9)
  line L4 (-1.5875, 173.45) -> (-1.5875, 88.9)
  line L5 (-1.5875, 88.9) -> (-1.5875, 139.7)
  line L6 (-92.6835, 104.5389) -> (0, 0)
  line L7 (-4.5875, -25.3213) -> (-4.5875, 172.5822)
  line L8 (25.9605, -24.7591) -> (-102.8492, 120.5272)
  line L9 (-76.3634, 103.2033) -> (8.4745, 7.5135)
  line L10 (-12.9131, 88.9) -> (-12.9131, 127.7323)
  circle C1 centre (0, 0) radius 90.4875
  circle C2 centre (0, 0) radius 88.9
  circle C3 centre (0, 0) radius 90.4875
  circle C4 centre (0, 0) radius 88.9
  circle C5 centre (0, 0) radius 88.9
  arc A1 centre (0, 0) radius 139.709 clockwise from (-92.6835, 104.5389) to (-1.5875, 139.7)
  arc A2 centre (0, 0) radius 88.9 clockwise from (-58.9766, 66.5205) to (-1.5872, 88.8858)
  arc A3 centre (0, 0) radius 91.9 clockwise from (-60.9668, 68.7653) to (-1.6408, 91.8854)
  arc A4 centre (0, 0) radius 128.3834 clockwise from (-76.3634, 103.2033) to (-12.9131, 127.7323)
  point P9 (-1.5875, 139.7)
  point P8 (-1.5875, 88.9)
  point P10 (-1.5875, 88.9)
  point P4 (0, 0)
  point P11 (0, 0)
  point P13 (0, 0)
  point P12 (-92.6835, 104.5389)
  point P14 (-92.6835, 104.5389)
  point P17 (-58.9766, 66.5205)
  point P15 (0, 0)
  coincident L4 P9
  coincident P8 P10
  perpendicular L3 L5
  coincident P4 P11
  coincident P11 P13
  coincident P12 P14
  coincident L6 P17
  coincident C4 P17
  coincident P13 P15
  vertical L7
  parallel L6 L8
  dimension "d736" distance P9 P10 = 50.8
  dimension "d737" distance L5 L7 = 3
  dimension "d738" distance L6 L8 = 3 (= "d737")
  dimension "d739" = 3
  dimension "d750" = 11.3256
extrude "Extrude6" new body sketch "aft reif jig" profile of C1 C2 C3 C4 C5 L3 L4 L5 L6 A1 A2 L7 L8 A3 along normal blind 63.5
extrude "Extrude7" sketch "aft reif jig" profile of A1 L7 L8 A3 L10 A4 L9 blind -3
work_plane "WorkPlane27"
sketch "Sketch63" plane through (-47.5024, 0, 123.0694) normal (-0.3601, 0, 0.9329) x axis (0, -1, 0)
  dimension "d745" = 10.0076
emboss "Emboss1" sketch "Sketch63" Depth 3 Horizontal Distance 0 Vertical Distance 0 Rotation Angle 0
remove_body "RemoveBody2"
work_plane "WorkPlane25"
sketch "aft handle tube moch" plane through (-1.5875, 0, 0) normal (1, 0, 0) x axis (0, 1, 0)
  line L1 (465.9763, 95.25) -> (461.9462, 95.25)
  line L2 (456.3769, 173.4306) -> (465.9763, 95.25)
  line L3 (456.3769, 173.4306) -> (405.5769, 173.4306)
  line L4 (322.4775, 173.4306) -> (405.5769, 173.4306)
  line L5 (322.4775, 169.45) -> (322.4775, 173.4306)
  line L6 (322.8085, 169.45) -> (322.4775, 169.45)
  line L7 (322.8085, 169.4293) -> (322.8085, 169.45)
  line L8 (410.0982, 169.4293) -> (322.8085, 169.4293)
  line L9 (410.0982, 169.4293) -> (452.8382, 169.4293)
  line L10 (461.9462, 95.25) -> (452.8382, 169.4293)
  line L11 (347.7775, 159.7411) -> (347.7775, 165.0751)
  line L12 (432.5812, 162.4081) -> (347.7775, 162.4081)
  line L13 (452.8994, 111.3178) -> (448.3379, 148.4677)
  line L14 (368.3024, 93.5081) -> (437.1427, 93.5081)
  line L15 (420.2823, 86.4868) -> (463.0222, 86.4868)
  line L16 (243.9207, 165.0751) -> (347.7775, 165.0751)
  line L17 (243.9207, 159.7411) -> (243.9207, 165.0751)
  line L18 (347.7775, 159.7411) -> (243.9207, 159.7411)
  line L19 (347.7775, 165.0751) -> (347.7775, 159.7411)
  line L20 (321.7775, 83.3621) -> (321.7775, 192.1338)
  line L21 (319.7775, 137.65) -> (319.7775, 135.65)
  line L22 (432.5812, 158.6616) -> (347.7775, 158.6616)
  line L23 (449.1808, 110.8612) -> (444.6193, 148.0111)
  line L24 (368.3024, 97.2546) -> (437.1427, 97.2546)
  line L25 (453.0558, 95.3043) -> (439.397, 107.3887)
  line L26 (440.6178, 155.6168) -> (443.1003, 158.4227)
  line L27 (414.2801, 135.3707) -> (322.4775, 135.3707)
  line L28 (399.9477, 144.4893) -> (434.5757, 148.7873)
  line L29 (399.9477, 144.4893) -> (365.4219, 149.543)
  line L30 (330.8961, 144.4893) -> (365.4219, 149.543)
  line L31 (283.2405, 162.4081) -> (347.7775, 162.4081)
  arc A1 centre (432.5812, 146.5331) radius 15.875 clockwise from (432.5812, 162.4081) to (448.3379, 148.4677)
  arc A2 centre (437.1427, 109.3831) radius 15.875 clockwise from (452.8994, 111.3178) to (437.1427, 93.5081)
  circle C1 centre (330.8961, 144.4893) radius 5.9436
  arc A3 centre (432.5812, 146.5331) radius 12.1285 clockwise from (432.5812, 158.6616) to (444.6193, 148.0111)
  arc A4 centre (437.1427, 109.3831) radius 12.1285 clockwise from (449.1808, 110.8612) to (437.1427, 97.2546)
  circle C2 centre (330.8961, 144.4893) radius 9.1186
  circle C3 centre (365.4219, 149.543) radius 9.1186
  circle C4 centre (399.9477, 144.4893) radius 9.1186
  circle C5 centre (439.397, 107.3887) radius 9.1186
  circle C6 centre (434.5757, 148.7873) radius 9.1186
  point P15 (432.5812, 162.4081)
  point P20 (432.5812, 162.4081)
  point P16 (448.3379, 148.4677)
  point P19 (448.3379, 148.4677)
  point P14 (347.7775, 162.4081)
  point P17 (452.8994, 111.3178)
  point P21 (452.8994, 111.3178)
  point P12 (347.7775, 165.0751)
  point P27 (347.7775, 165.0751)
  point P13 (347.7775, 159.7411)
  point P47 (439.397, 107.3887)
  point P48 (439.397, 107.3887)
  point P50 (449.0324, 98.864)
  point P52 (443.1003, 158.4227)
  point P53 (440.6178, 155.6168)
  point P51 (434.5757, 148.7873)
  point P56 (434.5757, 148.7873)
  point P46 (399.9477, 144.4893)
  point P57 (399.9477, 144.4893)
  point P45 (365.4219, 149.543)
  point P58 (365.4219, 149.543)
  point P59 (399.9477, 144.4893)
  point P60 (365.4219, 149.543)
  point P35 (330.8961, 144.4893)
  point P61 (330.8961, 144.4893)
  perpendicular L11 L12
  parallel L10 L13
  coincident P15 P20
  coincident P16 P19
  tangent L13 A1
  tangent L12 A1
  midpoint L11 P14
  coincident P17 P21
  parallel L14 L15
  tangent A2 L14
  tangent L13 A2
  horizontal L16
  vertical L17
  horizontal L18
  vertical L19
  coincident P12 P27
  coincident P13 L18
  vertical L20
  coincident P47 P48
  midpoint A4 L25
  midpoint A2 P50
  coincident L25 P50
  tangent A4 C5
  equal C2 C5
  equal C3 C5
  equal C3 C4
  equal C4 C6
  midpoint A1 P52
  midpoint A3 P53
  coincident C6 P53
  coincident P51 L26
  tangent L20 C2
  tangent C2 L27
  tangent L22 C3
  tangent C4 L27
  coincident P51 P56
  coincident P46 P57
  coincident P45 P58
  coincident P46 P59
  coincident P45 P60
  coincident P35 P61
  equal L29 L30
  equal L28 L29
  perpendicular L11 L31
  dimension "d623" radius A1 = 15.875 (= "( 1.25 / 2 ) * 1 in")
  dimension "d624" distance L8 L12 = 7.0213
  dimension "d625" distance L10 L13 = 7.0213 (= "d624")
  dimension "d626" radius A2 = 15.875 (= "( 1.25 / 2 ) * 1 in")
  dimension "d627" distance L14 L15 = 7.0213 (= "d625")
  dimension "d628" distance L20 L21 = 2
  dimension "d648" diameter C1 = 11.8872 (= "big_nut")
  dimension "d649" = 3.7465 (= "( 0.295 / 2 ) * 1 in")
  dimension "d650" = 3.175
extrude "Extrude15" add sketch "aft handle tube moch" profile of C2 C3 C4 C6 against normal blind 13.97
extrude "Extrude16" add sketch "aft handle tube moch" profile of C5 against normal blind 19.05
hole "Hole2" HoleDepth 25.4 HoleDiameter 6.65 (= "0.25 in + 0.3 mm") TipAngle 180
sketch "Sketch9" plane through (-1.5875, 0, 0) normal (1, 0, 0) x axis (0, 1, 0)
  line L1 (330.8961, 116.0727) -> (330.8961, 179.869)
  line L2 (365.4219, 106.8849) -> (365.4219, 179.7864)
  line L3 (399.9477, 105.2633) -> (399.9477, 188.5392)
  line L4 (473.3101, 111.3382) -> (406.2156, 103.5244)
  line L5 (443.8015, 69.5688) -> (430.1543, 186.7517)
  line L6 (434.5757, 148.7873) -> (399.9477, 144.4893)
  line L7 (365.4219, 149.543) -> (399.9477, 144.4893)
  line L8 (330.8961, 144.4893) -> (365.4219, 149.543)
  line L9 (466.9339, 148.7873) -> (434.5757, 148.7873)
  circle C1 centre (330.8961, 144.4893) radius 3.325
  circle C2 centre (330.8961, 144.4893) radius 9.1186
  circle C3 centre (365.4219, 149.543) radius 3.325
  circle C4 centre (365.4219, 149.543) radius 9.1186
  circle C5 centre (399.9477, 144.4893) radius 3.325
  circle C6 centre (399.9477, 144.4893) radius 9.1186
  circle C7 centre (434.5757, 148.7873) radius 3.325
  circle C8 centre (434.5757, 148.7873) radius 9.1186
  circle C9 centre (439.397, 107.3887) radius 3.325
  circle C10 centre (439.397, 107.3887) radius 9.1186
  point P2 (330.8961, 144.4893)
  point P13 (365.4219, 149.543)
  point P14 (399.9477, 144.4893)
  point P15 (434.5757, 148.7873)
  point P16 (439.397, 107.3887)
  point P17 (399.9477, 144.4893)
  point P18 (434.5757, 148.7873)
  point P19 (399.9477, 144.4893)
  point P20 (365.4219, 149.543)
  point P21 (365.4219, 149.543)
  point P22 (330.8961, 144.4893)
  vertical L2
  vertical L3
  coincident P2 L1
  coincident L2 P13
  coincident L3 P14
  coincident L5 P15
  coincident L5 P16
  coincident P14 P17
  coincident L5 P18
  coincident P15 P18
  coincident P14 P19
  coincident P13 P20
  coincident P13 P21
  coincident P2 P22
  vertical L1
  coincident L4 P16
  perpendicular L4 L5
  horizontal L9
web "Web3" Thickness 3 DraftAngle 0 FilletRadius 0
remove_body "RemoveBody3"
mirror "Mirror2" mirrorStitchTolerance 0.1016 bodies "left"
work_plane "WorkPlane3" AlongDistance -3.937 (= "( -0.31 / 2 ) * 1 in")
sketch "Sketch10" plane through (3.937, 0, 0) normal (-1, 0, 0) x axis (0, -1, 0)
  line L1 (-368.3024, 93.5081) -> (-437.1427, 93.5081)
  line L2 (-452.8994, 111.3178) -> (-448.3379, 148.4677)
  line L3 (-432.5812, 162.4081) -> (-347.7775, 162.4081)
  line L4 (-283.2405, 162.4081) -> (-347.7775, 162.4081)
  arc A1 centre (-437.1427, 109.3831) radius 15.875
  arc A2 centre (-432.5812, 146.5331) radius 15.875 clockwise from (-448.3379, 148.4677) to (-432.5812, 162.4081)
pipe "Pipe2" SectionSize 5.334 SectionThickness 1.3335
sketch "trig piv bolt" plane through (-5.5, 0, 0) normal (1, 0, 0) x axis (0, 1, 0)
  circle C1 centre (264.4867, 126.45) radius 4.6
  circle C2 centre (264.4867, 126.45) radius 1.65
  concentric C1 C2
  dimension "d629" diameter C2 = 3.3
extrude "Extrude12" cut sketch "trig piv bolt" profile of C2 along normal blind 43.18 and against normal blind 20.32
sketch "Sketch3" plane through (5, 0, 0) normal (1, 0, 0) x axis (0, 1, 0)
  line L1 (315.5775, 141.85) -> (319.7775, 137.65)
  line L2 (296.5763, 141.85) -> (315.5775, 141.85)
  line L3 (279.0207, 162.9256) -> (296.5763, 141.85)
  line L4 (263.8509, 141.85) -> (270.1342, 165.3063)
  line L5 (260.0435, 127.6406) -> (263.8509, 141.85)
  line L6 (272.0357, 136.85) -> (268.93, 125.2594)
  line L7 (278.9967, 136.85) -> (272.0357, 136.85)
  line L8 (278.9967, 123.4258) -> (278.9967, 136.85)
  line L9 (313.4688, 135.65) -> (313.4688, 131.35)
  line L10 (319.7775, 135.65) -> (313.4688, 135.65)
  line L11 (319.7775, 137.65) -> (319.7775, 135.65)
  arc A1 centre (264.4867, 126.45) radius 39.2645 clockwise from (270.1342, 165.3063) to (279.0207, 162.9256)
  arc A2 centre (264.4867, 126.45) radius 4.6 clockwise from (268.93, 125.2594) to (260.0435, 127.6406)
  arc A3 centre (274.4187, 51.1532) radius 72.4175 clockwise from (278.9967, 123.4258) to (311.5111, 113.35)
  arc A4 centre (229.7424, 131.35) radius 83.7264 clockwise from (313.4688, 131.35) to (311.5111, 113.35)
  circle C1 centre (264.4867, 126.45) radius 1.65
  circle C2 centre (264.4867, 126.45) radius 1.65
  concentric C1 C2
  dimension "d709" diameter C2 = 3.3
extrude "Extrude7" cut sketch "Sketch3" profile of C1 C2 against normal blind 10.0076
sketch "Sketch55" plane through (5.5, 0, 0) normal (-1, 0, 0) x axis (0, -1, 0)
  circle C1 centre (-264.4867, 126.45) radius 2.9
  circle C2 centre (-264.4867, 126.45) radius 1.65
  circle C3 centre (-264.4867, 126.45) radius 4.6
  circle C4 centre (-264.4867, 126.45) radius 1.65
  circle C5 centre (-264.4867, 126.45) radius 4.6
  concentric C1 C2
  dimension "d638" diameter C1 = 5.8
extrude "Extrude13" cut sketch "Sketch55" profile of C2 C1 blind -11.43 from offset -5
sketch "Sketch56" plane through (-5.5, 0, 0) normal (1, 0, 0) x axis (0, 1, 0)
  line L1 (266.3631, 129.7) -> (268.2395, 126.45)
  line L2 (262.6103, 129.7) -> (266.3631, 129.7)
  line L3 (260.7339, 126.45) -> (262.6103, 129.7)
  line L4 (262.6103, 123.2) -> (260.7339, 126.45)
  line L5 (266.3631, 123.2) -> (262.6103, 123.2)
  line L6 (268.2395, 126.45) -> (266.3631, 123.2)
  circle C1 centre (264.4867, 126.45) radius 1.65
  circle C2 centre (264.4867, 126.45) radius 4.6
  point P2 (264.4867, 126.45)
  point P9 (264.4867, 126.45)
  coincident P2 P9
  horizontal L5
  dimension "d642" distance P9 L6 = 3.25 (= "( 5.5 mm + 1 mm ) / 2")
extrude "Extrude14" cut sketch "Sketch56" profile of C1 L1 L2 L3 L4 L5 L6 blind -16.51 from offset -5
